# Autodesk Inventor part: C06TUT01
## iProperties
Created: 2009-04
Part Number: C06TUT01
Document SubType Name: Modeling
Designer: Sham
Density: 1 g/cm^3
Author: Sham
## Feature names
1. Extrusion1
2. Extrusion2
3. Extrusion3
4. Extrusion4
5. Extrusion5
6. Fillet1
7. Extrusion6
8. Extrusion7
